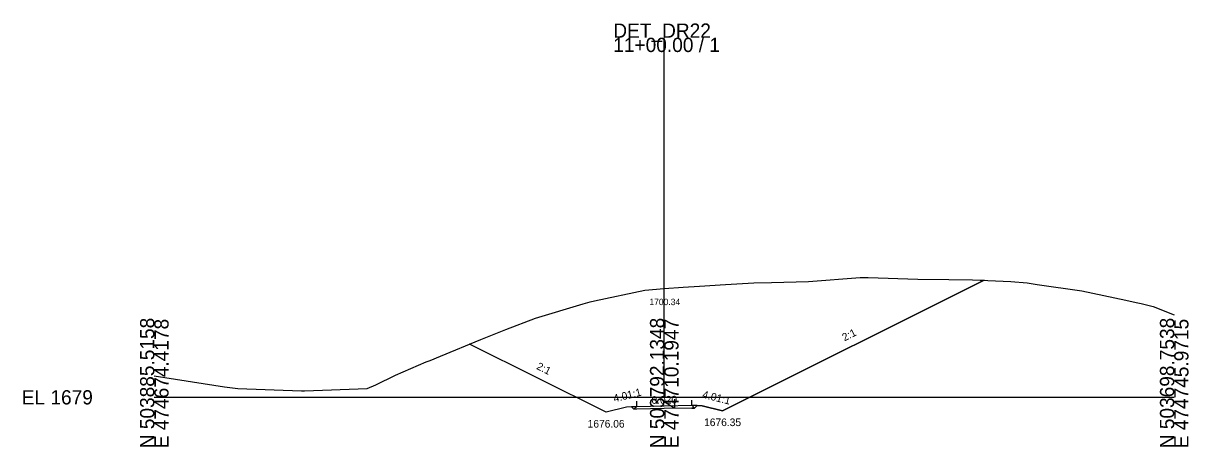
# Model space of a CAD drawing. Extents: x -26 to 1203, y -10 to 9633.
# Drawn here: x -25.7 to 202.8, y 2490.3 to 2573.4 of the extents above; entities that cross this region are included whole.
import ezdxf

# ---------------------------------------------------------------- set-up
doc = ezdxf.new("R2010")
doc.units = 0
for name, color, linetype in [('Exist Cross Section Cell', 7, 'Continuous'), ('Exist XS Center Line Elevation Label', 7, 'Continuous'), ('Exist XS Ground Line', 7, 'Continuous'), ('Prop XS Ditch Slope Text', 7, 'Continuous'), ('Prop XS Ditch Standard Text', 7, 'Continuous'), ('Prop XS Earthwork Shape', 7, 'Continuous'), ('Prop XS EOT Tick Mark', 7, 'Continuous'), ('Prop XS Finish Grade', 7, 'Continuous'), ('Prop XS Finish Grade Earthwork', 7, 'Continuous'), ('Prop XS Finish Grade Pavement', 7, 'Continuous'), ('Prop XS Pvmt Edge Slope', 7, 'Continuous'), ('Prop XS SE Text', 7, 'Continuous'), ('Prop XS Shoulder Borrow Shape', 7, 'Continuous'), ('Prop XS Side Slope Text', 7, 'Continuous'), ('Prop XS Subgrade Earthwork', 7, 'Continuous')]:
    doc.layers.add(name, color=color, linetype=linetype)

msp = doc.modelspace()

# ---------------------------------------------------------------- linework, layer by layer
at = {"layer": 'Exist Cross Section Cell'}
for p, q in [((100, 2500), (100, 2570.56)), ((0, 2500), (100, 2500)), ((100, 2500), (200, 2500))]:
    msp.add_line(p, q, dxfattribs=at)
at = {"layer": 'Exist XS Ground Line'}
msp.add_lwpolyline([(0, 2504.19), (13.78, 2502.09), (16.36, 2501.7), (28.89, 2501.26), (29.46, 2501.26), (41.75, 2501.71), (43.42, 2502.45), (47.32, 2504.34), (53.33, 2506.97), (54.1, 2507.25), (56.11, 2508.05), (64.04, 2511.32), (68.96, 2513.3), (74.75, 2515.53), (84.07, 2518.35), (85.46, 2518.76), (86.32, 2518.93), (96.17, 2521.05), (100, 2521.34), (103.69, 2521.62), (106.88, 2521.83), (112.03, 2522.11), (117.59, 2522.46), (121.05, 2522.56), (128.3, 2522.75), (138.41, 2523.51), (139.01, 2523.52), (139.98, 2523.5), (149.73, 2523.16), (155.78, 2523.12), (160.44, 2523.06), (167.94, 2522.71), (171.15, 2522.47), (173.14, 2522.17), (181.86, 2520.92), (190.5, 2519.05), (192.57, 2518.61), (193.49, 2518.38), (195.9, 2517.84), (200, 2516.2)], dxfattribs=at)
at = {"layer": 'Prop XS Earthwork Shape'}
msp.add_lwpolyline([(100, 2497.78), (94.59, 2497.68), (94.04, 2497.66), (93.57, 2498.14), (92.59, 2498.06), (88.58, 2497.06), (61.83, 2510.41), (64.04, 2511.32), (68.96, 2513.3), (74.75, 2515.53), (84.07, 2518.35), (85.46, 2518.76), (86.32, 2518.93), (96.17, 2521.05), (100, 2521.34), (103.69, 2521.62), (106.88, 2521.83), (112.03, 2522.11), (117.59, 2522.46), (121.05, 2522.56), (128.3, 2522.75), (138.41, 2523.51), (139.01, 2523.52), (139.98, 2523.5), (149.73, 2523.16), (155.78, 2523.12), (160.44, 2523.06), (162.71, 2522.96), (111.42, 2497.35), (107.41, 2498.35), (106.43, 2498.39), (105.94, 2497.9), (105.41, 2497.89)], close=True, dxfattribs=at)
at = {"layer": 'Prop XS EOT Tick Mark'}
for p, q in [((94.59, 2498.22), (94.59, 2499.22)), ((105.41, 2498.43), (105.41, 2499.43))]:
    msp.add_line(p, q, dxfattribs=at)
at = {"layer": 'Prop XS Finish Grade'}
for p, q in [((94.59, 2498.22), (93.57, 2498.14)), ((105.41, 2498.43), (106.43, 2498.39))]:
    msp.add_line(p, q, dxfattribs=at)
at = {"layer": 'Prop XS Finish Grade Earthwork'}
for p, q in [((111.42, 2497.35), (162.71, 2522.96)), ((88.58, 2497.06), (61.83, 2510.41)), ((92.59, 2498.06), (88.58, 2497.06)), ((93.57, 2498.14), (92.59, 2498.06)), ((106.43, 2498.39), (107.41, 2498.35)), ((107.41, 2498.35), (111.42, 2497.35))]:
    msp.add_line(p, q, dxfattribs=at)
at = {"layer": 'Prop XS Finish Grade Pavement'}
for p, q in [((94.59, 2498.22), (100, 2498.33)), ((100, 2498.33), (105.41, 2498.43))]:
    msp.add_line(p, q, dxfattribs=at)
at = {"layer": 'Prop XS Pvmt Edge Slope'}
for p, q in [((94.59, 2498.22), (94.04, 2497.66)), ((105.41, 2498.43), (105.94, 2497.9))]:
    msp.add_line(p, q, dxfattribs=at)
at = {"layer": 'Prop XS Shoulder Borrow Shape'}
for points in [[(94.59, 2498.22), (94.04, 2497.66), (93.57, 2498.14)], [(105.94, 2497.9), (106.43, 2498.39), (105.41, 2498.43)]]:
    msp.add_lwpolyline(points, close=True, dxfattribs=at)
at = {"layer": 'Prop XS Subgrade Earthwork'}
for p, q in [((94.04, 2497.66), (93.57, 2498.14)), ((105.41, 2497.89), (100, 2497.78)), ((105.41, 2497.89), (105.94, 2497.9)), ((105.94, 2497.9), (106.43, 2498.39)), ((94.59, 2497.68), (94.04, 2497.66)), ((100, 2497.78), (94.59, 2497.68))]:
    msp.add_line(p, q, dxfattribs=at)

# ---------------------------------------------------------------- texts
at = {"layer": 'Exist Cross Section Cell'}
for s, p in [('DET_DR22', (90, 2570.56)), ('11+00.00 / 1', (90, 2567.76)), ('EL 1679', (-26, 2498.6))]:
    msp.add_text(s, height=2.8, dxfattribs=at).set_placement(p)
for s, p in [('N 503885.5158', (0, 2490)), ('E 474674.4178', (2.8, 2490)), ('N 503792.1348', (100, 2490)), ('E 474710.1947', (102.8, 2490)), ('N 503698.7538', (200, 2490)), ('E 474745.9715', (202.8, 2490))]:
    msp.add_text(s, height=2.8, rotation=90, dxfattribs=at).set_placement(p)
at = {"layer": 'Exist XS Center Line Elevation Label'}
msp.add_text('1700.34', height=1.25, dxfattribs=at).set_placement((97.08, 2518.09))
at = {"layer": 'Prop XS Ditch Slope Text'}
for rotation, p in [(14.012, (90.22, 2499.01)), (345.988, (107.36, 2499.91))]:
    msp.add_text('4.01:1', height=1.5, rotation=rotation, dxfattribs=at).set_placement(p)
at = {"layer": 'Prop XS Ditch Standard Text'}
for s, p in [('1676.06', (84.97, 2494.06)), ('1676.35', (107.81, 2494.35))]:
    msp.add_text(s, height=1.5, dxfattribs=at).set_placement(p)
at = {"layer": 'Prop XS SE Text'}
msp.add_text('0.020', height=1.5, rotation=1.1458, dxfattribs=at).set_placement((97.5, 2498.71))
at = {"layer": 'Prop XS Side Slope Text'}
for rotation, p in [(26.5237, (135.33, 2510.97)), (333.4763, (74.81, 2505.61))]:
    msp.add_text('2:1', height=1.5, rotation=rotation, dxfattribs=at).set_placement(p)

doc.saveas('drawing.dxf')
